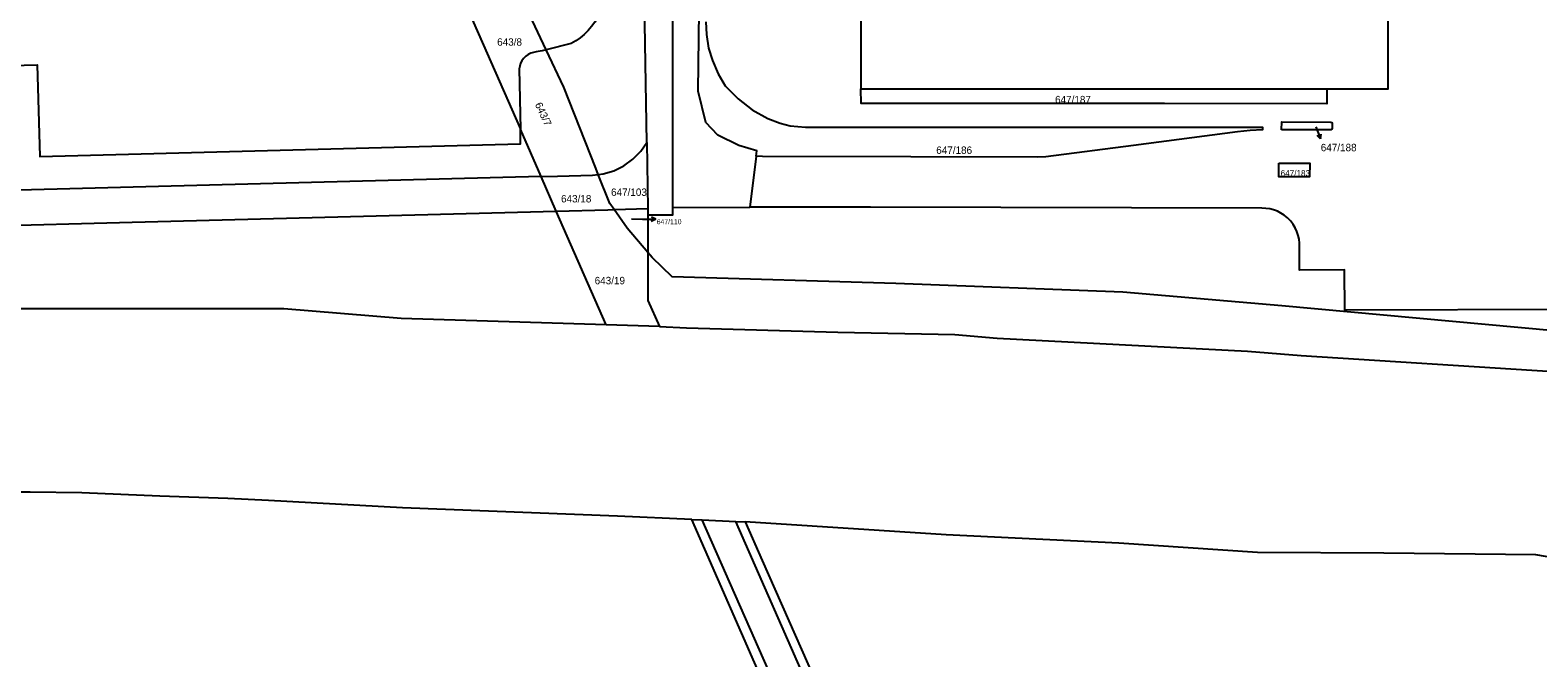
# Model space of a CAD drawing. Extents: x -724107 to -720612, y -1045267 to -1038441.
# Drawn here: x -723237.1 to -722891.5, y -1041870.1 to -1041726.2 of the extents above; entities that cross this region are included whole.
import ezdxf

# ---------------------------------------------------------------- set-up
doc = ezdxf.new("R2010")
doc.units = 0
for name, color, linetype in [('Hranice parcel', 7, 'Continuous'), ('Parcelní čísla', 7, 'Continuous'), ('Pop  PČ popisy', 7, 'Continuous'), ('Vnitřní kresba', 7, 'Continuous')]:
    doc.layers.add(name, color=color, linetype=linetype)

msp = doc.modelspace()

# ---------------------------------------------------------------- linework, layer by layer
at = {"layer": 'Hranice parcel'}
for p, q in [((-723089.77, -1041766.88), (-723089.77, -1041523.63)), ((-723046.73, -1041655.02), (-723046.74, -1041739.65)), ((-723113.13, -1041729.3), (-723118.84, -1041730.73)), ((-723125.02, -1041735.08), (-723124.76, -1041748.9)), ((-723046.74, -1041739.65), (-722939.86, -1041739.66)), ((-723119.99, -1041759.78), (-723124.76, -1041748.9)), ((-723095.8, -1041751.98), (-723095.54, -1041767.14)), ((-723070.7, -1041755.11), (-723072.15, -1041766.8)), ((-723116.52, -1041767.69), (-723119.99, -1041759.78)), ((-723105.05, -1041793.81), (-723116.52, -1041767.69)), ((-723103.28, -1041767.34), (-723095.54, -1041767.14)), ((-723095.54, -1041767.14), (-723095.52, -1041768.57)), ((-723095.52, -1041768.57), (-723095.52, -1041777.18)), ((-723089.77, -1041766.88), (-723072.15, -1041766.8)), ((-723095.52, -1041777.18), (-723095.52, -1041788.2)), ((-723095.52, -1041788.2), (-723092.89, -1041794.18)), ((-723092.89, -1041794.18), (-723105.05, -1041793.81)), ((-723027.06, -1041971.47), (-723085.48, -1041838.4)), ((-723073.19, -1041838.97), (-723069.29, -1041847.83))]:
    msp.add_line(p, q, dxfattribs=at)
for points in [[(-723070.7, -1041755.11), (-723070.55, -1041753.88), (-723074.66, -1041752.64), (-723079.52, -1041750.32), (-723082.25, -1041747.43), (-723083.97, -1041740.18), (-723083.49, -1041697.27), (-723083.38, -1041606.71), (-723082.77, -1041523.63)], [(-723095.8, -1041751.98), (-723096.7, -1041697.42), (-723097.2, -1041601.31), (-723097.03, -1041527.91)], [(-722939.86, -1041739.66), (-722925.82, -1041739.66), (-722925.83, -1041649.5)], [(-723118.84, -1041730.73), (-723125.85, -1041715.76), (-723126.91, -1041717.15), (-723134.66, -1041699.55)], [(-723139.24, -1041715.91), (-723134.36, -1041727.04), (-723124.76, -1041748.9)], [(-723105.12, -1041715.76), (-723105.16, -1041716.99), (-723105.29, -1041718.21), (-723105.52, -1041719.42), (-723105.85, -1041720.61), (-723106.28, -1041721.76), (-723106.8, -1041722.88), (-723107.06, -1041723.35), (-723107.7, -1041724.4), (-723108.43, -1041725.39), (-723109.24, -1041726.32), (-723110.12, -1041727.18), (-723111.06, -1041727.97), (-723112.07, -1041728.68), (-723113.13, -1041729.3)], [(-723082.26, -1041724.32), (-723082.12, -1041727.19), (-723081.63, -1041730.35), (-723080.74, -1041733.18), (-723079.44, -1041736.23), (-723077.78, -1041739), (-723074.81, -1041741.96), (-723071.58, -1041744.47), (-723067.99, -1041746.5), (-723065.2, -1041747.58), (-723062.89, -1041748.17), (-723059.41, -1041748.46), (-723046.72, -1041748.46), (-723005.42, -1041748.44), (-722954.65, -1041748.47), (-722954.62, -1041749.09), (-722957.44, -1041749.21), (-722960.36, -1041749.54), (-722984.19, -1041752.64), (-723004.28, -1041755.24), (-723006.25, -1041755.34), (-723035.28, -1041755.25), (-723069.28, -1041755.19), (-723070.7, -1041755.11)], [(-723121.12, -1041731.21), (-723121.76, -1041731.31), (-723122.39, -1041731.51), (-723122.97, -1041731.8), (-723123.5, -1041732.18), (-723123.58, -1041732.24), (-723124.04, -1041732.71), (-723124.42, -1041733.24), (-723124.71, -1041733.82), (-723124.91, -1041734.44), (-723125.02, -1041735.08)], [(-723118.84, -1041730.73), (-723119.79, -1041730.97), (-723121.12, -1041731.21)], [(-723106.89, -1041759.3), (-723107.46, -1041757.86), (-723114.82, -1041739.33), (-723118.84, -1041730.73)], [(-723432.98, -1041739.38), (-723428.39, -1041739.25), (-723428.28, -1041741.24), (-723410.79, -1041740.79), (-723410.28, -1041759.72), (-723382.91, -1041758.8), (-723359.02, -1041758.18), (-723359.55, -1041739.42), (-723304.72, -1041737.99), (-723304.78, -1041735.96), (-723235.48, -1041734.16), (-723234.87, -1041755.15), (-723124.7, -1041752.31), (-723124.76, -1041748.9)], [(-722939.86, -1041739.66), (-722939.87, -1041743.14), (-722977.13, -1041743.03), (-723005.22, -1041743.07), (-723046.65, -1041743.06), (-723046.74, -1041739.65)], [(-722950.24, -1041749.07), (-722950.21, -1041747.27), (-722938.99, -1041747.28), (-722938.73, -1041747.39), (-722938.63, -1041747.64), (-722938.64, -1041748.72), (-722938.74, -1041748.94), (-722939, -1041749.07), (-722950.24, -1041749.07)], [(-723106.89, -1041759.3), (-723105.81, -1041759.18), (-723103.34, -1041758.46), (-723101.03, -1041757.33), (-723098.95, -1041755.82), (-723097.16, -1041753.98), (-723095.8, -1041751.98)], [(-722950.86, -1041756.75), (-722943.8, -1041756.73), (-722943.84, -1041759.86), (-722950.86, -1041759.88), (-722950.86, -1041756.75)], [(-723119.99, -1041759.78), (-723207.71, -1041762.09), (-723306.66, -1041764.69), (-723310.89, -1041764.62), (-723315.11, -1041764.2), (-723320.37, -1041763.16), (-723324.54, -1041762.38), (-723328.75, -1041761.95), (-723332.99, -1041761.88), (-723431.01, -1041764.47)], [(-723119.99, -1041759.78), (-723116.22, -1041759.68), (-723108.2, -1041759.45), (-723106.89, -1041759.3)], [(-723103.28, -1041767.34), (-723104.26, -1041765.97), (-723106.89, -1041759.3)], [(-723712.21, -1041783.39), (-723592.8, -1041780.24), (-723472.83, -1041777.07), (-723352.87, -1041773.91), (-723213.72, -1041770.25), (-723116.52, -1041767.69)], [(-723116.52, -1041767.69), (-723104.69, -1041767.38), (-723103.28, -1041767.34)], [(-723095.52, -1041777.18), (-723100.25, -1041771.62), (-723103.28, -1041767.34)], [(-723095.52, -1041768.57), (-723089.77, -1041768.57), (-723089.77, -1041766.88)], [(-722954.8, -1041767.07), (-723044.47, -1041766.84), (-723072.15, -1041766.8)], [(-722946.18, -1041775.99), (-722946.17, -1041775.08), (-722946.26, -1041774.16), (-722946.45, -1041773.27), (-722946.73, -1041772.4), (-722947.11, -1041771.57), (-722947.58, -1041770.78), (-722948.13, -1041770.05), (-722948.28, -1041769.87), (-722948.93, -1041769.22), (-722949.64, -1041768.65), (-722950.41, -1041768.15), (-722951.23, -1041767.75), (-722952.09, -1041767.43), (-722952.98, -1041767.21), (-722953.89, -1041767.09), (-722954.8, -1041767.07)], [(-722771.31, -1041772.71), (-722771.31, -1041773.33), (-722771.28, -1041782.26), (-722771.25, -1041789.87), (-722882.9, -1041790.26), (-722883.07, -1041790.26), (-722884.05, -1041790.26), (-722935.79, -1041790.41), (-722935.85, -1041781.15), (-722946.16, -1041781.28), (-722946.18, -1041775.99)], [(-722572.15, -1041790.09), (-722572.74, -1041789.71), (-722582.1, -1041791.68), (-722592.36, -1041792.63), (-722601.62, -1041793.62), (-722636.53, -1041797.02), (-722697.04, -1041802.03), (-722736.46, -1041801.53), (-722782.47, -1041798.74), (-722864.18, -1041795.53), (-722887.81, -1041795.13), (-722950.17, -1041789.44), (-722986.65, -1041786.31), (-723038.66, -1041784.3), (-723089.92, -1041782.77), (-723094.54, -1041778.33), (-723095.52, -1041777.18)], [(-723105.05, -1041793.81), (-723152.1, -1041792.36), (-723178.99, -1041790.1), (-723244.11, -1041790.08), (-723274.23, -1041789.44), (-723362.89, -1041792.17), (-723402.65, -1041789.9), (-723412.36, -1041789.59), (-723435.37, -1041789.54), (-723463.99, -1041791.35), (-723492.96, -1041792.22), (-723525.76, -1041793.03), (-723539.57, -1041793.26), (-723582.6, -1041795.32), (-723607.97, -1041794.61), (-723623.81, -1041796.19), (-723657.27, -1041798.33), (-723677.88, -1041801.08), (-723705.76, -1041801.7), (-723711.68, -1041802)], [(-723092.89, -1041794.18), (-723086.7, -1041794.44), (-723051.97, -1041795.48), (-723025.14, -1041796.02), (-723015.49, -1041796.83), (-722958.04, -1041799.79), (-722945.78, -1041800.8), (-722888.1, -1041804.49), (-722773.91, -1041807.27), (-722760.61, -1041808.06), (-722735.26, -1041809.9), (-722679.21, -1041814.75)], [(-723085.48, -1041838.4), (-723102.45, -1041837.63), (-723151.78, -1041835.73), (-723182.48, -1041834.05), (-723191.82, -1041833.57), (-723207.41, -1041833.08), (-723225.26, -1041832.31), (-723237.11, -1041832.16), (-723246.15, -1041832.16), (-723289.38, -1041833.42), (-723316.66, -1041832.67), (-723353.98, -1041834.29), (-723373.31, -1041835.1), (-723418.56, -1041837.73), (-723430.6, -1041838.61), (-723456.02, -1041839.83), (-723473.38, -1041841.38), (-723536.94, -1041847.93), (-723558.84, -1041849.62), (-723572.63, -1041850.33), (-723585.59, -1041851.54), (-723600.31, -1041853.1), (-723625.34, -1041858.47)], [(-723085.48, -1041838.4), (-723083.06, -1041838.51), (-723075.37, -1041838.87), (-723073.19, -1041838.97)], [(-722832.37, -1041853.47), (-722855.71, -1041848.29), (-722874.36, -1041849.54), (-722891.97, -1041846.49), (-722926.79, -1041846.16), (-722955.75, -1041845.99), (-722987.54, -1041843.83), (-723027.13, -1041841.89), (-723073.19, -1041838.97)], [(-723069.29, -1041847.83), (-723033.27, -1041929.43), (-723004.05, -1041995.81)]]:
    msp.add_lwpolyline(points, dxfattribs=at)
at = {"layer": 'Pop  PČ popisy'}
for p, q in [((-722942.37, -1041748.35), (-722941.3, -1041751.15)), ((-722941.3, -1041751.15), (-722942.12, -1041750.4)), ((-722941.3, -1041751.15), (-722941.19, -1041750.04)), ((-723099.29, -1041769.49), (-723096.73, -1041769.53)), ((-723093.73, -1041769.58), (-723094.72, -1041769.06)), ((-723096.73, -1041769.53), (-723093.73, -1041769.58)), ((-723093.73, -1041769.58), (-723094.74, -1041770.07))]:
    msp.add_line(p, q, dxfattribs=at)
at = {"layer": 'Vnitřní kresba'}
for p, q in [((-723024.92, -1041970.53), (-723083.06, -1041838.51)), ((-723035.12, -1041930.25), (-723075.37, -1041838.87))]:
    msp.add_line(p, q, dxfattribs=at)

# ---------------------------------------------------------------- texts
at = {"layer": 'Parcelní čísla'}
for s, height, p in [('643/8', 1.7, (-723130.07, -1041729.79)), ('647/187', 1.7, (-723002.18, -1041742.99)), ('647/188', 1.7, (-722941.28, -1041753.98)), ('647/186', 1.7, (-723029.42, -1041754.59)), ('647/183', 1.394, (-722950.47, -1041759.71)), ('647/103', 1.7, (-723103.97, -1041764.22)), ('643/18', 1.7, (-723115.43, -1041765.72)), ('647/110', 1.139, (-723093.5, -1041770.71)), ('643/19', 1.7, (-723107.72, -1041784.48))]:
    msp.add_text(s, height=height, dxfattribs=at).set_placement(p)
msp.add_text('643/7', height=1.7, rotation=295, dxfattribs=at).set_placement((-723121.46, -1041743.25))

doc.saveas('drawing.dxf')
